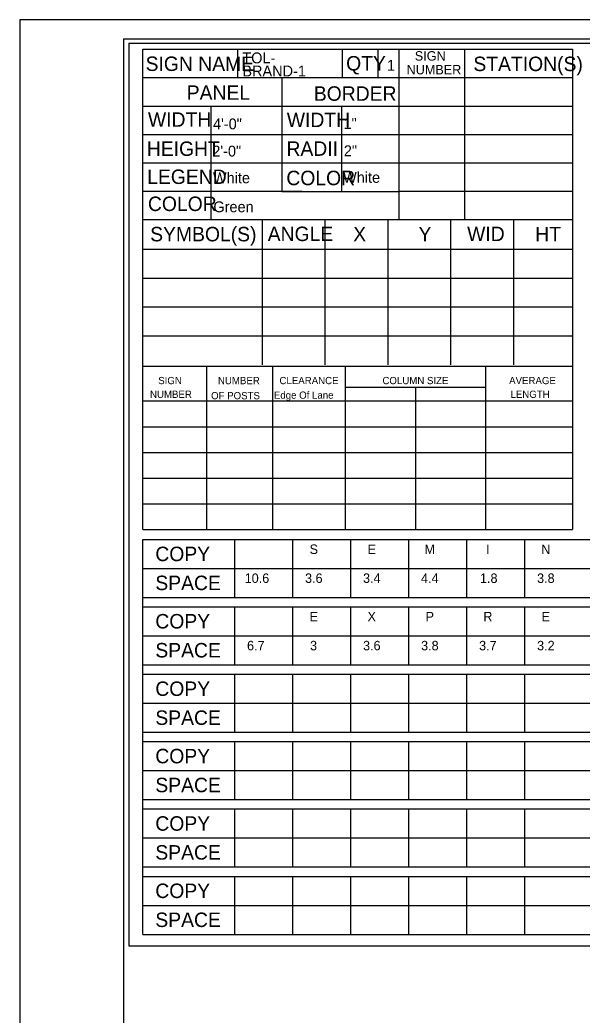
# Model space of a CAD drawing. Extents: x 17890587 to 17890754, y 17897693 to 17897992.
# Drawn here: x 17890586.76 to 17890595.51, y 17897888.71 to 17897904.2 of the extents above; entities that cross this region are included whole.
import ezdxf

# ---------------------------------------------------------------- set-up
doc = ezdxf.new("R2010")
doc.units = 0
for name, color, linetype in [('GSSign', 7, 'Continuous'), ('PlotBorder_dp', 7, 'Continuous'), ('SheetBorder_dp', 7, 'Continuous'), ('SheetLinesMisc2_dp', 7, 'Continuous'), ('TextMinor', 7, 'Continuous')]:
    doc.layers.add(name, color=color, linetype=linetype)

msp = doc.modelspace()

# ---------------------------------------------------------------- linework, layer by layer
at = {"layer": 'PlotBorder_dp'}
msp.add_lwpolyline([(17890586.756, 17897873.104), (17890635.165, 17897873.104), (17890635.165, 17897904.203), (17890586.756, 17897904.203)], close=True, dxfattribs=at)
at = {"layer": 'SheetBorder_dp'}
for q in [(17890588.37, 17897873.397), (17890633.551, 17897903.909)]:
    msp.add_line((17890588.37, 17897903.909), q, dxfattribs=at)
at = {"layer": 'SheetLinesMisc2_dp'}
for p, q in [((17890588.454, 17897903.839), (17890611.019, 17897903.839)), ((17890588.454, 17897903.839), (17890588.454, 17897889.792)), ((17890588.67, 17897896.269), (17890588.67, 17897903.746)), ((17890588.67, 17897903.746), (17890595.362, 17897903.746)), ((17890590.145, 17897903.746), (17890590.145, 17897903.304)), ((17890591.772, 17897903.746), (17890591.772, 17897903.304)), ((17890592.328, 17897903.746), (17890592.328, 17897903.304)), ((17890592.659, 17897903.746), (17890592.659, 17897901.096)), ((17890593.677, 17897903.746), (17890593.677, 17897901.096)), ((17890595.362, 17897903.746), (17890595.362, 17897896.269)), ((17890588.67, 17897903.304), (17890595.362, 17897903.304)), ((17890590.833, 17897903.304), (17890590.833, 17897901.533)), ((17890588.67, 17897902.862), (17890595.362, 17897902.862)), ((17890589.728, 17897902.862), (17890589.728, 17897901.096)), ((17890591.766, 17897902.858), (17890591.766, 17897901.533)), ((17890588.67, 17897902.421), (17890595.362, 17897902.421)), ((17890588.67, 17897901.979), (17890595.362, 17897901.979)), ((17890588.67, 17897901.538), (17890591.152, 17897901.538)), ((17890590.833, 17897901.533), (17890592.659, 17897901.533)), ((17890592.659, 17897901.538), (17890595.362, 17897901.538)), ((17890588.67, 17897901.096), (17890595.362, 17897901.096)), ((17890590.529, 17897901.087), (17890590.529, 17897898.832)), ((17890591.506, 17897901.087), (17890591.506, 17897898.832)), ((17890592.484, 17897901.087), (17890592.484, 17897898.832)), ((17890593.462, 17897901.087), (17890593.462, 17897898.832)), ((17890594.44, 17897901.087), (17890594.44, 17897898.832)), ((17890588.672, 17897900.636), (17890595.362, 17897900.636)), ((17890588.672, 17897900.185), (17890595.362, 17897900.185)), ((17890588.672, 17897899.734), (17890595.362, 17897899.734)), ((17890588.672, 17897899.283), (17890595.362, 17897899.283)), ((17890588.67, 17897898.811), (17890595.362, 17897898.811)), ((17890589.663, 17897898.811), (17890589.663, 17897896.269)), ((17890590.69, 17897898.811), (17890590.69, 17897896.269)), ((17890591.823, 17897898.811), (17890591.823, 17897896.269)), ((17890594.005, 17897898.811), (17890594.005, 17897896.269)), ((17890591.823, 17897898.488), (17890594.004, 17897898.488)), ((17890592.918, 17897898.488), (17890592.918, 17897896.269)), ((17890588.67, 17897898.272), (17890595.362, 17897898.272)), ((17890588.67, 17897897.871), (17890595.362, 17897897.871)), ((17890588.67, 17897897.471), (17890595.362, 17897897.471)), ((17890588.67, 17897897.07), (17890595.362, 17897897.07)), ((17890588.67, 17897896.67), (17890595.362, 17897896.67)), ((17890588.67, 17897896.269), (17890595.362, 17897896.269)), ((17890588.67, 17897896.115), (17890610.866, 17897896.115)), ((17890588.67, 17897889.969), (17890588.67, 17897896.115)), ((17890590.099, 17897896.115), (17890590.099, 17897895.213)), ((17890591.002, 17897896.115), (17890591.002, 17897895.213)), ((17890591.905, 17897896.115), (17890591.905, 17897895.213)), ((17890592.808, 17897896.115), (17890592.808, 17897895.213)), ((17890593.71, 17897896.115), (17890593.71, 17897895.213)), ((17890594.613, 17897896.115), (17890594.613, 17897895.213)), ((17890588.67, 17897895.664), (17890610.866, 17897895.664)), ((17890588.67, 17897895.213), (17890610.866, 17897895.213)), ((17890588.67, 17897895.066), (17890610.866, 17897895.066)), ((17890590.099, 17897895.066), (17890590.099, 17897894.164)), ((17890591.002, 17897895.066), (17890591.002, 17897894.164)), ((17890591.905, 17897895.066), (17890591.905, 17897894.164)), ((17890592.808, 17897895.066), (17890592.808, 17897894.164)), ((17890593.71, 17897895.066), (17890593.71, 17897894.164)), ((17890594.613, 17897895.066), (17890594.613, 17897894.164)), ((17890588.67, 17897894.615), (17890610.866, 17897894.615)), ((17890588.67, 17897894.164), (17890610.866, 17897894.164)), ((17890588.67, 17897894.017), (17890610.866, 17897894.017)), ((17890590.099, 17897894.017), (17890590.099, 17897893.116)), ((17890591.002, 17897894.017), (17890591.002, 17897893.116)), ((17890591.905, 17897894.017), (17890591.905, 17897893.116)), ((17890592.808, 17897894.017), (17890592.808, 17897893.116)), ((17890593.71, 17897894.017), (17890593.71, 17897893.116)), ((17890594.613, 17897894.017), (17890594.613, 17897893.116)), ((17890588.67, 17897893.566), (17890610.866, 17897893.566)), ((17890588.67, 17897893.116), (17890610.866, 17897893.116)), ((17890588.67, 17897892.969), (17890610.866, 17897892.969)), ((17890590.099, 17897892.969), (17890590.099, 17897892.067)), ((17890591.002, 17897892.969), (17890591.002, 17897892.067)), ((17890591.905, 17897892.969), (17890591.905, 17897892.067)), ((17890592.808, 17897892.969), (17890592.808, 17897892.067)), ((17890593.71, 17897892.969), (17890593.71, 17897892.067)), ((17890594.613, 17897892.969), (17890594.613, 17897892.067)), ((17890588.67, 17897892.518), (17890610.866, 17897892.518)), ((17890588.67, 17897892.067), (17890610.866, 17897892.067)), ((17890588.67, 17897891.92), (17890610.866, 17897891.92)), ((17890590.099, 17897891.92), (17890590.099, 17897891.018)), ((17890591.002, 17897891.92), (17890591.002, 17897891.018)), ((17890591.905, 17897891.92), (17890591.905, 17897891.018)), ((17890592.808, 17897891.92), (17890592.808, 17897891.018)), ((17890593.71, 17897891.92), (17890593.71, 17897891.018)), ((17890594.613, 17897891.92), (17890594.613, 17897891.018)), ((17890588.67, 17897891.469), (17890610.866, 17897891.469)), ((17890588.67, 17897891.018), (17890610.866, 17897891.018)), ((17890588.67, 17897890.871), (17890610.866, 17897890.871)), ((17890590.099, 17897890.871), (17890590.099, 17897889.969)), ((17890591.002, 17897890.871), (17890591.002, 17897889.969)), ((17890591.905, 17897890.871), (17890591.905, 17897889.969)), ((17890592.808, 17897890.871), (17890592.808, 17897889.969)), ((17890593.71, 17897890.871), (17890593.71, 17897889.969)), ((17890594.613, 17897890.871), (17890594.613, 17897889.969)), ((17890588.67, 17897890.42), (17890610.866, 17897890.42)), ((17890588.67, 17897889.969), (17890610.866, 17897889.969)), ((17890588.454, 17897889.792), (17890611.019, 17897889.792))]:
    msp.add_line(p, q, dxfattribs=at)

# ---------------------------------------------------------------- texts
at = {"layer": 'GSSign'}
for s, height, p in [('TOL-', 0.1687, (17890590.22, 17897903.527)), ('1', 0.169, (17890592.472, 17897903.412)), ('BRAND-1', 0.1687, (17890590.22, 17897903.323)), ('4\'-0"', 0.1687, (17890589.763, 17897902.5)), ('1"', 0.1687, (17890591.795, 17897902.506)), ('2\'-0"', 0.1687, (17890589.752, 17897902.076)), ('2"', 0.1687, (17890591.8, 17897902.081)), ('White', 0.1687, (17890589.762, 17897901.66)), ('White', 0.1687, (17890591.788, 17897901.667)), ('Green', 0.1687, (17890589.769, 17897901.209)), ('S', 0.147, (17890591.267, 17897895.89)), ('E', 0.147, (17890592.17, 17897895.89)), ('M', 0.147, (17890593.056, 17897895.89)), ('I', 0.147, (17890594.016, 17897895.89)), ('N', 0.147, (17890594.873, 17897895.89)), ('10.6', 0.147, (17890590.256, 17897895.439)), ('3.6', 0.147, (17890591.196, 17897895.439)), ('3.4', 0.147, (17890592.099, 17897895.439)), ('4.4', 0.147, (17890593.002, 17897895.439)), ('1.8', 0.147, (17890593.92, 17897895.439)), ('3.8', 0.147, (17890594.809, 17897895.439)), ('E', 0.147, (17890591.267, 17897894.841)), ('X', 0.147, (17890592.169, 17897894.841)), ('P', 0.147, (17890593.073, 17897894.841)), ('R', 0.147, (17890593.972, 17897894.841)), ('E', 0.147, (17890594.879, 17897894.841)), ('6.7', 0.147, (17890590.293, 17897894.39)), ('3', 0.147, (17890591.274, 17897894.39)), ('3.6', 0.147, (17890592.099, 17897894.39)), ('3.8', 0.147, (17890593.003, 17897894.39)), ('3.7', 0.147, (17890593.906, 17897894.39)), ('3.2', 0.147, (17890594.809, 17897894.39))]:
    msp.add_text(s, height=height, dxfattribs=at).set_placement(p)
at = {"layer": 'TextMinor'}
for s, height, p in [('SIGN', 0.147, (17890592.905, 17897903.569)), ('SIGN NAME', 0.225, (17890588.714, 17897903.408)), ('QTY', 0.225, (17890591.836, 17897903.415)), ('STATION(S)', 0.225, (17890593.817, 17897903.406)), ('NUMBER', 0.147, (17890592.777, 17897903.355)), ('PANEL', 0.225, (17890589.354, 17897902.959)), ('BORDER', 0.225, (17890591.333, 17897902.944)), ('WIDTH', 0.225, (17890588.75, 17897902.539)), ('WIDTH', 0.225, (17890590.912, 17897902.534)), ('HEIGHT', 0.225, (17890588.733, 17897902.086)), ('RADII', 0.225, (17890590.907, 17897902.087)), ('LEGEND', 0.225, (17890588.738, 17897901.649)), ('COLOR', 0.225, (17890590.905, 17897901.63)), ('COLOR', 0.225, (17890588.75, 17897901.228)), ('SYMBOL(S)', 0.225, (17890588.785, 17897900.756)), ('ANGLE', 0.225, (17890590.615, 17897900.76)), ('X', 0.225, (17890591.946, 17897900.756)), ('Y', 0.225, (17890592.963, 17897900.756)), ('WID', 0.225, (17890593.72, 17897900.76)), ('HT', 0.225, (17890594.78, 17897900.756)), ('SIGN', 0.1125, (17890588.91, 17897898.533)), ('NUMBER', 0.1125, (17890589.84, 17897898.532)), ('CLEARANCE', 0.1125, (17890590.798, 17897898.533)), ('COLUMN SIZE', 0.11249, (17890592.401, 17897898.533)), ('AVERAGE', 0.1125, (17890594.374, 17897898.533)), ('NUMBER', 0.1125, (17890588.782, 17897898.319)), ('Edge Of Lane', 0.11249, (17890590.711, 17897898.306)), ('LENGTH', 0.1125, (17890594.395, 17897898.319)), ('OF POSTS', 0.1125, (17890589.733, 17897898.298)), ('COPY', 0.225, (17890588.865, 17897895.778)), ('SPACE', 0.225, (17890588.865, 17897895.327)), ('COPY', 0.225, (17890588.865, 17897894.73)), ('SPACE', 0.225, (17890588.865, 17897894.279)), ('COPY', 0.225, (17890588.865, 17897893.68)), ('SPACE', 0.225, (17890588.865, 17897893.229)), ('COPY', 0.225, (17890588.865, 17897892.631)), ('SPACE', 0.225, (17890588.865, 17897892.181)), ('COPY', 0.225, (17890588.865, 17897891.582)), ('SPACE', 0.225, (17890588.865, 17897891.132)), ('COPY', 0.225, (17890588.865, 17897890.534)), ('SPACE', 0.225, (17890588.865, 17897890.083))]:
    msp.add_text(s, height=height, dxfattribs=at).set_placement(p)

doc.saveas('drawing.dxf')
